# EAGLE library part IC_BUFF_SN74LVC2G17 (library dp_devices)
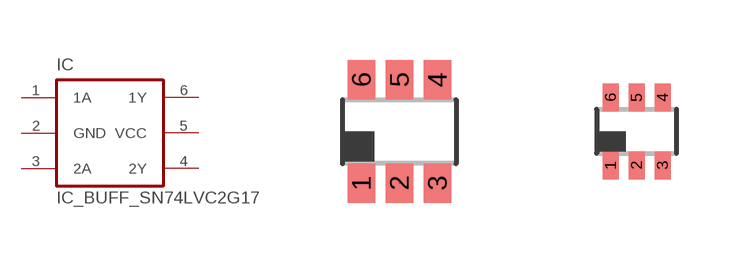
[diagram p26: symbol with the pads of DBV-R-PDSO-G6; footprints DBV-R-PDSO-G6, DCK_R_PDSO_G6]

Designator prefix IC

## IC_BUFF_SN74LVC2G17DBV  [DBV-R-PDSO-G6]
1  1A
2  GND
3  2A
4  2Y
5  VCC
6  1Y

## IC_BUFF_SN74LVC2G17DCK  [DCK_R_PDSO_G6]
Pads as for DBV-R-PDSO-G6

## Footprint DBV-R-PDSO-G6 (pad centres in mm)
smd 0.69 x 0.99: 1 -0.95,-1.29; 2 0,-1.29; 3 0.95,-1.29; 4 0.95,1.3; 5 0,1.3; 6 -0.95,1.3

## Footprint DCK_R_PDSO_G6 (pad centres in mm)
smd 0.4 x 0.7: 1 -0.65,-0.85; 2 0,-0.85; 3 0.65,-0.85; 4 0.65,0.85; 5 0,0.85; 6 -0.65,0.85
